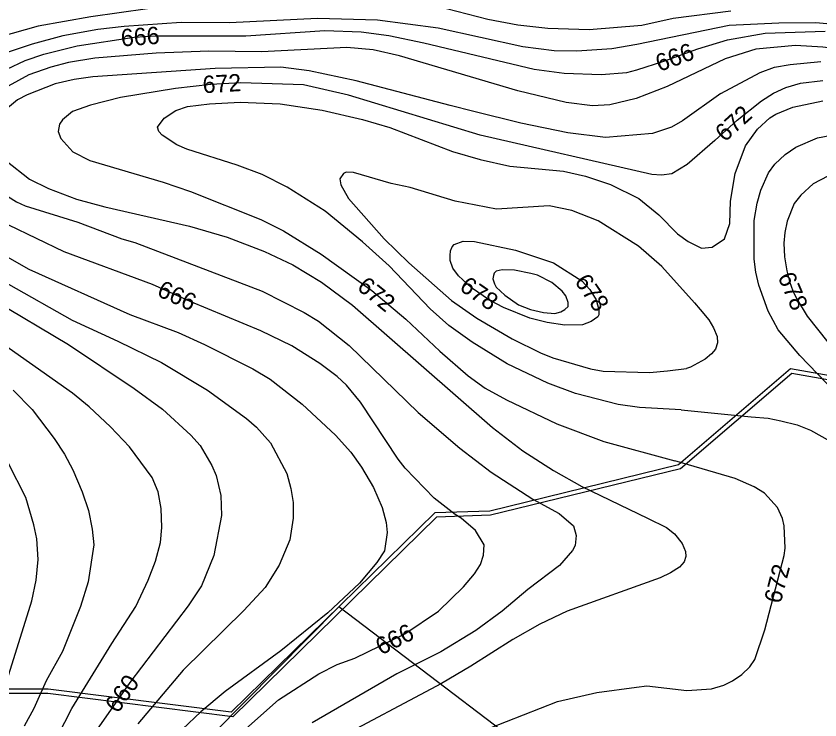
# Model space of a CAD drawing. Extents: x -709418 to -703832, y -1161719 to -1157826.
# Drawn here: x -707148 to -706777, y -1161364.7 to -1161039.8 of the extents above; entities that cross this region are included whole.
import ezdxf

# ---------------------------------------------------------------- set-up
doc = ezdxf.new("R2010")
doc.units = 0
for name, color, linetype in [('120_vrstevnice hlavní', 7, 'Continuous'), ('121_vrstevnice hlavní_popis', 7, 'Continuous'), ('122_vrstevnice základní', 7, 'Continuous'), ('124_vrstevnice doplňková', 7, 'Continuous'), ('603_NRBK_stav', 7, 'Continuous'), ('609_LBC_stav', 7, 'Continuous')]:
    doc.layers.add(name, color=color, linetype=linetype)

msp = doc.modelspace()

# ---------------------------------------------------------------- linework, layer by layer
at = {"layer": '120_vrstevnice hlavní'}
for points in [[(-706822.81, -1161075.51), (-706804.64, -1161065.86), (-706797.94, -1161063.44), (-706790.81, -1161062.15), (-706776.57, -1161060.73)], [(-706822.81, -1161075.52), (-706840.44, -1161088.15), (-706845.56, -1161091), (-706854.24, -1161094.04), (-706875.94, -1161095.92), (-706893.3, -1161093.75), (-706914.99, -1161089.26), (-706936.69, -1161083.91), (-706947.68, -1161081.02), (-706991.08, -1161069.74), (-707012.77, -1161065.11), (-707025.79, -1161063.37), (-707056.17, -1161063.95), (-707112.58, -1161067.85), (-707121.26, -1161069.01), (-707129.94, -1161071.04), (-707142.95, -1161076.1), (-707147.29, -1161078.41), (-707154.67, -1161084.49)], [(-707152.79, -1161106.48), (-707141.8, -1161115.01), (-707133.12, -1161119.35), (-707120.1, -1161124.27), (-707107.08, -1161127.88), (-707068.03, -1161136.85), (-707050.67, -1161141.91), (-707033.31, -1161148.42), (-707020.3, -1161154.64), (-707006.99, -1161162.6), (-706992.81, -1161173.3), (-706928.16, -1161229.71), (-706914.13, -1161240.42), (-706899.95, -1161249.53), (-706886.93, -1161256.91), (-706856.56, -1161271.51), (-706847.79, -1161275.8)], [(-707158.58, -1161170.84), (-707123.86, -1161191.38), (-707093.48, -1161211.78), (-707080.47, -1161221.18), (-707067.3, -1161233.18), (-707063.11, -1161237.96), (-707057.61, -1161247.21), (-707055.73, -1161251.84), (-707053.56, -1161261.1), (-707053.27, -1161270.36), (-707056.74, -1161288.87), (-707062.39, -1161302.76), (-707068.61, -1161312.02), (-707095.51, -1161347.45), (-707126.03, -1161390.99)], [(-706847.79, -1161275.8), (-706844.1, -1161278.85), (-706840.59, -1161283.26), (-706839.04, -1161286.89), (-706838.83, -1161289.27), (-706839.66, -1161291.66), (-706841.87, -1161294.23), (-706845.94, -1161296.79), (-706850.7, -1161299.11)], [(-706850.7, -1161299.11), (-706893.73, -1161314.47), (-706906.32, -1161320.55), (-706918.81, -1161327.54), (-706938.14, -1161339.93), (-706951.73, -1161347.89), (-707003.23, -1161375.22)]]:
    msp.add_lwpolyline(points, dxfattribs=at)
for points in [[(-706822.81, -1161075.51), (-706822.81, -1161075.52)], [(-706847.79, -1161275.8), (-706847.79, -1161275.8)], [(-706850.7, -1161299.11), (-706850.7, -1161299.11)]]:
    msp.add_open_spline(points, degree=1, dxfattribs=at)
at = {"layer": '122_vrstevnice základní'}
for points in [[(-706818.07, -1161037.49), (-706844.79, -1161040.89), (-706859.16, -1161044.13), (-706883.46, -1161046.16), (-706902.55, -1161045.58), (-706916.44, -1161043.99), (-706930.33, -1161041.39), (-706949.42, -1161036.47), (-706966.92, -1161033.14), (-706984.13, -1161031.55), (-706998.02, -1161031.11), (-707023.77, -1161031.98), (-707087.41, -1161036.47), (-707113.45, -1161040.08), (-707137.75, -1161044.42), (-707162.05, -1161051.22)], [(-706818.9, -1161044.11), (-706861.47, -1161052.96), (-706873.05, -1161054.84), (-706889.25, -1161055.99), (-706899.66, -1161055.85), (-706914.13, -1161053.97), (-706953.18, -1161045.44), (-706981.24, -1161041.67), (-707008.87, -1161040.95), (-707049.51, -1161042.98), (-707071.79, -1161042.83), (-707098.11, -1161044.57), (-707110.26, -1161046.01), (-707126.46, -1161048.91), (-707140.64, -1161052.81), (-707166.96, -1161061.49)], [(-706766.88, -1161044.06), (-706778.85, -1161042.92), (-706795.94, -1161043.06), (-706818.9, -1161044.11)], [(-707143.82, -1161060.33), (-707135.14, -1161057.44), (-707119.81, -1161053.54), (-707093.48, -1161049.49), (-707083.36, -1161048.91), (-707041.99, -1161048.91), (-707005.54, -1161046.45), (-706988.76, -1161047.03), (-706976.03, -1161048.76), (-706959.83, -1161052.09), (-706908.92, -1161064.24), (-706895.03, -1161066.12), (-706877.97, -1161066.84), (-706866.1, -1161065.83), (-706861.47, -1161064.67), (-706849.01, -1161060.63), (-706833.4, -1161054.91), (-706819.72, -1161050.69)], [(-706819.72, -1161050.69), (-706802.21, -1161047.62), (-706774.57, -1161046.76)], [(-706501.55, -1161163.75), (-706537.18, -1161156.2), (-706559.97, -1161150.5), (-706569.95, -1161147.36), (-706601.3, -1161135.39), (-706622.39, -1161125.28), (-706632.22, -1161119.58), (-706647.75, -1161111.74), (-706704.18, -1161076.97), (-706718.71, -1161069.56), (-706741.8, -1161061.01), (-706752.2, -1161058.16), (-706764.31, -1161055.6), (-706775.71, -1161054.17), (-706788.28, -1161053.41), (-706806.56, -1161055.05), (-706820.81, -1161059.48)], [(-706820.81, -1161059.48), (-706847.59, -1161072.34), (-706861.76, -1161077.83), (-706873.92, -1161080.73), (-706882.02, -1161081.16), (-706894.17, -1161079.72), (-706916.44, -1161074.36), (-706971.12, -1161058.16), (-706983.27, -1161055.42), (-706995.42, -1161054.26), (-707034.76, -1161056.28), (-707059.06, -1161055.99), (-707083.36, -1161056.86), (-707111.71, -1161059.18), (-707123.86, -1161061.2), (-707131.96, -1161063.37), (-707142.09, -1161066.99), (-707158.29, -1161075.67)], [(-707152.35, -1161064.24), (-707143.82, -1161060.33)], [(-706825.52, -1161097.22), (-706838.33, -1161108.35), (-706845.42, -1161112.55), (-706850.19, -1161113.27), (-706854.53, -1161112.98), (-706933.8, -1161094.76), (-706994.55, -1161076.24), (-707015.38, -1161071.47), (-707044.31, -1161070.6), (-707058.19, -1161071.33), (-707074.39, -1161073.21), (-707099.85, -1161077.4), (-707113.73, -1161080.87), (-707121.98, -1161083.77), (-707126.61, -1161087.67), (-707127.91, -1161089.7), (-707128.67, -1161093.12), (-707127.41, -1161096.3), (-707121.86, -1161102.42), (-707114.02, -1161106.48), (-707080.18, -1161116.46), (-707067.45, -1161120.79), (-707035.05, -1161133.67), (-707024.63, -1161138.88), (-707007.28, -1161149.72), (-706983.84, -1161166.5), (-706968.08, -1161179.67), (-706952.46, -1161194.42), (-706939.29, -1161205.84), (-706931.48, -1161211.63), (-706921.65, -1161216.98), (-706898.5, -1161227.98), (-706876.81, -1161236.22), (-706843.96, -1161245.06)], [(-706825.52, -1161097.22), (-706815.18, -1161087.8), (-706803.92, -1161078.97), (-706798.51, -1161075.41), (-706792.81, -1161072.7), (-706785.97, -1161070.7), (-706775.71, -1161069.56)], [(-706831.71, -1161146.89), (-706826.72, -1161146.51), (-706821.02, -1161142.66), (-706818.6, -1161135.54), (-706818.32, -1161125.28), (-706816.18, -1161112.45), (-706811.33, -1161099.63), (-706805.78, -1161091.93), (-706800.08, -1161086.8), (-706797.37, -1161085.09), (-706789.53, -1161081.82), (-706775.71, -1161078.97)], [(-706841.03, -1161221.61), (-706860.36, -1161220.5), (-706870.15, -1161219.15), (-706889.83, -1161213.95), (-706902.55, -1161209.32), (-706921.36, -1161200.35), (-706937.56, -1161190.37), (-706948.26, -1161182.7), (-706956.94, -1161174.89), (-706975.89, -1161155.07), (-706988.18, -1161143.94), (-707005.4, -1161129.91), (-707022.9, -1161118.77), (-707034.47, -1161112.98), (-707046.04, -1161108.64), (-707069.19, -1161101.27), (-707073.81, -1161099.24), (-707080.61, -1161094.76), (-707082.2, -1161093.02), (-707082.78, -1161091), (-707079.74, -1161086.95), (-707074.25, -1161083.33), (-707068.9, -1161081.6), (-707058.77, -1161080.29), (-707044.6, -1161079.57), (-707026.08, -1161080.29), (-707006.7, -1161083.19), (-706988.18, -1161087.53), (-706975.46, -1161091.29), (-706946.53, -1161102.28), (-706933.8, -1161106.04), (-706920.2, -1161109.08), (-706895.32, -1161111.39), (-706885.2, -1161113.71), (-706873.62, -1161117.61), (-706860.61, -1161123.98), (-706851.35, -1161131.5), (-706842.67, -1161140.32), (-706837.75, -1161143.79), (-706831.71, -1161146.89)], [(-706753.62, -1161230.3), (-706786.25, -1161196.53), (-706796.23, -1161184.56), (-706800.93, -1161176.01), (-706805.21, -1161164.04), (-706806.63, -1161158.05), (-706807.34, -1161152.07), (-706807.34, -1161134.11), (-706805.92, -1161126.13), (-706804.21, -1161120.15), (-706800.79, -1161112.17), (-706797.8, -1161108.18), (-706793.09, -1161103.76), (-706788.11, -1161100.34), (-706778.13, -1161096.07), (-706769.16, -1161094.36)], [(-706834.88, -1161172.23), (-706849.98, -1161155.42), (-706860.75, -1161145.96), (-706879.41, -1161134.39), (-706891.56, -1161129.62), (-706901.98, -1161127.45), (-706926.28, -1161128.9), (-706945.37, -1161125.28), (-706966.2, -1161118.91), (-706974.88, -1161117.03), (-706992.23, -1161111.97), (-706995.71, -1161111.83), (-706996.86, -1161112.41), (-706998.6, -1161114.86), (-706998.16, -1161117.76), (-706994.55, -1161123.98), (-706978.2, -1161142.64), (-706966.78, -1161153.63), (-706947.1, -1161171.13), (-706935.39, -1161179.23), (-706919.04, -1161188.78), (-706906.03, -1161195.29), (-706900.24, -1161197.6), (-706882.88, -1161202.66), (-706877.1, -1161203.68), (-706855.69, -1161204.4), (-706847.3, -1161203.53), (-706838.64, -1161202.45)], [(-706773.43, -1161113.74), (-706780.13, -1161117.16), (-706785.83, -1161122.43), (-706788.96, -1161126.28), (-706792.1, -1161134.4), (-706793.21, -1161139.77), (-706793.66, -1161144.66), (-706793.38, -1161150.93), (-706792.29, -1161157.34), (-706791.1, -1161162.33), (-706789.53, -1161166.6), (-706787.83, -1161170.2), (-706782.84, -1161178.29), (-706773.43, -1161190.26)], [(-707158, -1161119.2), (-707147.87, -1161125.57), (-707143.82, -1161127.45), (-707119.52, -1161134.97), (-707099.27, -1161142.64), (-707093.2, -1161144.37), (-707034.47, -1161166.79), (-707015.09, -1161176.63), (-707008.43, -1161180.68), (-706994.26, -1161191.81), (-706962.44, -1161222.77), (-706943.2, -1161239.26), (-706928.73, -1161250.4), (-706909.5, -1161262.83), (-706897.35, -1161269.49), (-706890.69, -1161275.13), (-706889.54, -1161279.61), (-706889.97, -1161284.24), (-706891.13, -1161286.56), (-706897.2, -1161293.35), (-706911.81, -1161304.49), (-706923.67, -1161314.47), (-706935.82, -1161323.44), (-706952.02, -1161333.28), (-706972.27, -1161343.4), (-707011.33, -1161366.11)], [(-707041.99, -1161368.86), (-707026.95, -1161355.41), (-707008.29, -1161343.4), (-706999.76, -1161339.06), (-706991.66, -1161336.17), (-706968.66, -1161325.03), (-706953.03, -1161314.51), (-706941.46, -1161303.19), (-706936.4, -1161297.26), (-706933.65, -1161292.92), (-706932.21, -1161288.58), (-706931.92, -1161283.95), (-706935.97, -1161277.3), (-706942.62, -1161271.51), (-706945.37, -1161269.92), (-706955.06, -1161262.26), (-706968.37, -1161248.52), (-706971.69, -1161244.32), (-706989.05, -1161218), (-706995.56, -1161210.19), (-706999.76, -1161206.14), (-707007.85, -1161200.2), (-707020.73, -1161191.96), (-707035.05, -1161185.02), (-707067.74, -1161171.56), (-707085.1, -1161163.75), (-707125.89, -1161148.57), (-707151.34, -1161136.27)], [(-706941.61, -1161143.65), (-706936.4, -1161143.79), (-706917.45, -1161147.91), (-706899.95, -1161153.63), (-706886.93, -1161162.02), (-706883.17, -1161166.07), (-706880.28, -1161170.84), (-706878.98, -1161175.47), (-706878.98, -1161177.64), (-706879.56, -1161178.65), (-706882.59, -1161180.82), (-706886.64, -1161182.27), (-706894.74, -1161182.41), (-706902.84, -1161181.26), (-706910.94, -1161179.23), (-706923.09, -1161174.31), (-706929.46, -1161170.99), (-706937.85, -1161165.2), (-706943.78, -1161159.7), (-706946.38, -1161156.23), (-706947.64, -1161152.63), (-706947.68, -1161150.3), (-706947.53, -1161148.12), (-706946.67, -1161146.25), (-706945.8, -1161145.24), (-706941.61, -1161143.65)], [(-707155.39, -1161149.15), (-707142.09, -1161156.67), (-707095.51, -1161177.5), (-707073.23, -1161185.88), (-707061.08, -1161191.38), (-707038.81, -1161202.66), (-707030.71, -1161207.44), (-707015.96, -1161219.01), (-707000.62, -1161233.18), (-706993.54, -1161241.14), (-706988.62, -1161248.08), (-706983.12, -1161257.34), (-706979.07, -1161266.6), (-706977.19, -1161273.54), (-706976.76, -1161278.17), (-706977.91, -1161286.65), (-706981.44, -1161292.04), (-706989.48, -1161301.6), (-707004.09, -1161315.2), (-707025.79, -1161332.84), (-707051.54, -1161351.65), (-707062.82, -1161360.9), (-707071.21, -1161369)], [(-707151.49, -1161163.61), (-707122.12, -1161180.24), (-707101.01, -1161189.79), (-707080.9, -1161199.77), (-707059.64, -1161212.5), (-707041.7, -1161225.52), (-707037.07, -1161229.57), (-707030.56, -1161236.8), (-707023.04, -1161250.98), (-707021.16, -1161257.92), (-707020.15, -1161264.28), (-707020.15, -1161271.51), (-707021.74, -1161281.64), (-707026.66, -1161293.21), (-707033.02, -1161303.62), (-707042.86, -1161314.18), (-707070.92, -1161341.67), (-707091.89, -1161366.55)], [(-706834.87, -1161172.23), (-706832.24, -1161175.32), (-706828.34, -1161180), (-706826.14, -1161183.71), (-706824.44, -1161187.69), (-706824.33, -1161190.57), (-706825.25, -1161193.63), (-706827.01, -1161195.67), (-706830, -1161198.24), (-706836.79, -1161201.89), (-706838.64, -1161202.45)], [(-707135.43, -1161384.92), (-707122.27, -1161359.46), (-707103.9, -1161329.37), (-707092.76, -1161312.3), (-707086.98, -1161300.15), (-707083.65, -1161291.48), (-707081.33, -1161282.8), (-707080.76, -1161275.85), (-707081.05, -1161267.18), (-707082.49, -1161259.36), (-707085.24, -1161252.85), (-707095.65, -1161238.68), (-707104.48, -1161229.42), (-707114.31, -1161220.17), (-707121.98, -1161213.8), (-707161.76, -1161185.88)], [(-707149.32, -1161212.5), (-707140.64, -1161221.47), (-707130.51, -1161234.78), (-707125.74, -1161242.01), (-707121.84, -1161249.24), (-707117.49, -1161259.36), (-707114.6, -1161268.04), (-707112.87, -1161276.72), (-707112.14, -1161283.95), (-707114.75, -1161301.02), (-707118.22, -1161312.3), (-707126.61, -1161333.13), (-707134.13, -1161346.73), (-707139.77, -1161359.46), (-707144.26, -1161367.56)], [(-706841.03, -1161221.61), (-706808.77, -1161224.74), (-706800.88, -1161225.47), (-706795.09, -1161226.59), (-706787.48, -1161228.53), (-706781.41, -1161231.01), (-706772.29, -1161236)], [(-707155.25, -1161355.99), (-707140.78, -1161309.7), (-707138.76, -1161300.15), (-707137.89, -1161290.61), (-707138.47, -1161281.06), (-707139.77, -1161274.7), (-707143.53, -1161261.97), (-707151.63, -1161246.06)], [(-706856.92, -1161348.95), (-706838.41, -1161351.13), (-706827.01, -1161350.28), (-706821.41, -1161348.62), (-706817.32, -1161346.71), (-706813.01, -1161343.78), (-706809.34, -1161340.16), (-706807.06, -1161336.74), (-706802.36, -1161323.06), (-706793.52, -1161288.86), (-706793.09, -1161285.44), (-706793.52, -1161275.18), (-706794.23, -1161271.76), (-706796.66, -1161266.63), (-706802.64, -1161260.08), (-706807.34, -1161257.08), (-706816.18, -1161253.24), (-706843.96, -1161245.06)], [(-706929.46, -1161368.57), (-706898.07, -1161356.13), (-706879.99, -1161352.08), (-706861.64, -1161349.56), (-706856.92, -1161348.95)]]:
    msp.add_lwpolyline(points, dxfattribs=at)
for points in [[(-706818.9, -1161044.11), (-706818.9, -1161044.11)], [(-706819.72, -1161050.69), (-706819.72, -1161050.69)], [(-706820.81, -1161059.48), (-706820.81, -1161059.48)], [(-706825.52, -1161097.22), (-706825.52, -1161097.22)], [(-706831.71, -1161146.89), (-706831.71, -1161146.89)], [(-706834.87, -1161172.23), (-706834.88, -1161172.23)], [(-706838.64, -1161202.45), (-706838.64, -1161202.45)], [(-706841.03, -1161221.61), (-706841.03, -1161221.61)], [(-706843.96, -1161245.06), (-706843.96, -1161245.06)], [(-706856.92, -1161348.95), (-706856.92, -1161348.95)]]:
    msp.add_open_spline(points, degree=1, dxfattribs=at)
at = {"layer": '124_vrstevnice doplňková'}
msp.add_lwpolyline([(-706910.39, -1161158.68), (-706917.94, -1161157.14), (-706923.61, -1161156.86), (-706926.39, -1161157.59), (-706927.37, -1161158.54), (-706927.65, -1161159.55), (-706928.04, -1161161.11), (-706927.14, -1161163.47), (-706926.42, -1161164.91), (-706922.5, -1161168.63), (-706916.06, -1161173.04), (-706910.64, -1161175.31), (-706904.54, -1161176.69), (-706899.3, -1161177.02), (-706896.57, -1161176.37), (-706894.76, -1161175.31), (-706893.13, -1161173.9), (-706893.13, -1161171.96), (-706894.26, -1161168.95), (-706896.01, -1161166.81), (-706900.81, -1161162.83), (-706907.31, -1161159.4), (-706910.39, -1161158.68)], dxfattribs=at)
at = {"layer": '603_NRBK_stav'}
for points in [[(-706131.54, -1161182.12), (-706202.13, -1161217.39), (-706268.61, -1161173.09), (-706340.02, -1161149.3), (-706456.57, -1161150.94), (-706463.14, -1161228.06), (-706515.67, -1161223.14), (-706619.09, -1161232.98), (-706790.64, -1161202.63), (-706842.35, -1161246.93), (-706929.35, -1161268.26), (-706954.8, -1161269.08), (-707048.73, -1161361.19), (-707133.27, -1161350.52), (-707242.44, -1161350.52), (-707314.67, -1161334.11), (-707345.86, -1161311.96)], [(-706130.65, -1161183.91), (-706202.27, -1161219.7), (-706269.5, -1161174.9), (-706340.33, -1161151.3), (-706454.74, -1161152.91), (-706461.32, -1161230.24), (-706515.67, -1161225.15), (-706619.17, -1161235), (-706790.05, -1161204.76), (-706841.41, -1161248.76), (-706929.08, -1161270.25), (-706953.95, -1161271.06), (-707048.02, -1161363.29), (-707133.4, -1161352.52), (-707242.66, -1161352.52), (-707315.5, -1161335.98), (-707347.46, -1161313.28)]]:
    msp.add_lwpolyline(points, dxfattribs=at)
at = {"layer": '609_LBC_stav'}
msp.add_lwpolyline([(-706889.48, -1161634.04), (-706881.6, -1161401.81), (-706999.13, -1161312.56), (-707158.25, -1161473.24), (-707262.12, -1161523.52), (-707321.32, -1161551.38), (-707332.71, -1161630.23)], dxfattribs=at)

# ---------------------------------------------------------------- texts
at = {"layer": '121_vrstevnice hlavní_popis'}
for s, rotation, p in [('666', 4.1624, (-707099.36, -1161053.84)), ('666', 20.4515, (-706851.03, -1161065.63)), ('672', 3.3158, (-707061.71, -1161075.43)), ('672', 42.0992, (-706820.89, -1161098.24)), ('672', 320.9074, (-706991.12, -1161165.64)), ('678', 325.3284, (-706943.86, -1161165.98)), ('678', 304.3752, (-706890.51, -1161162.29)), ('678', 293.1632, (-706796.62, -1161160.06)), ('666', 335.4, (-707083.47, -1161168.75)), ('672', 75.6177, (-706795.17, -1161311.38)), ('666', 26.5165, (-706979.55, -1161334.97)), ('660', 54.5785, (-707101.08, -1161362.07))]:
    msp.add_text(s, height=8, rotation=rotation, dxfattribs=at).set_placement(p)

doc.saveas('drawing.dxf')
